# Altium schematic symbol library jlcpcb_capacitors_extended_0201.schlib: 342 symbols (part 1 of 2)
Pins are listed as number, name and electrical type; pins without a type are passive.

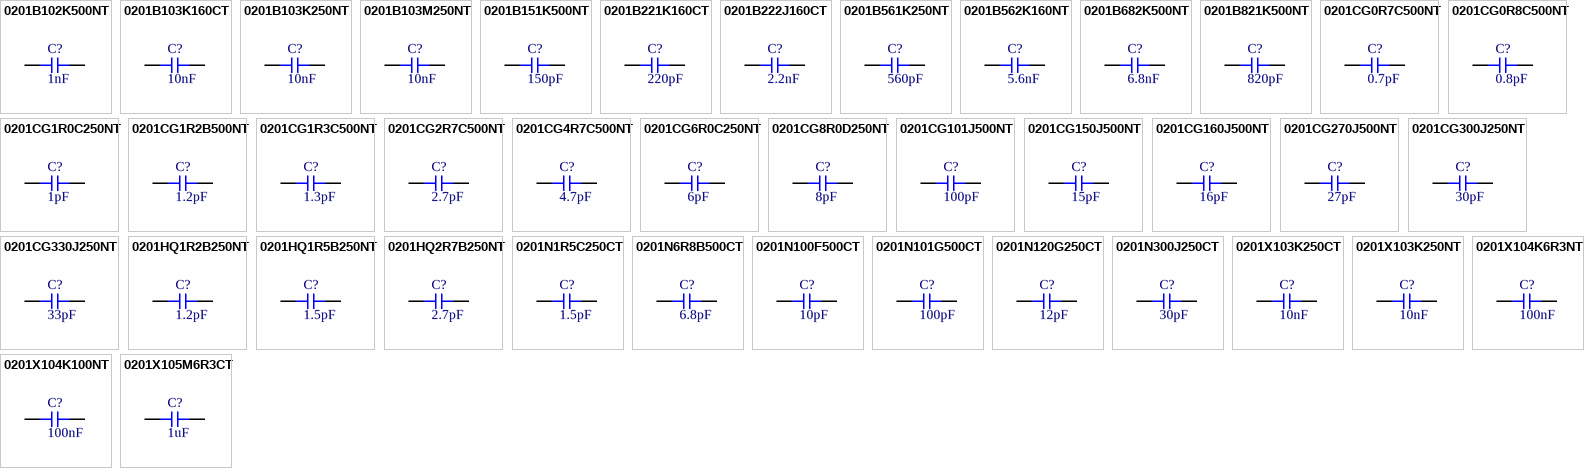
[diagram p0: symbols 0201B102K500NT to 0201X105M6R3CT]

## 0201B102K500NT
designator C?  Capacitance: 1nF  (hidden comment: *)
Capacitor, Ceramic (MLCC), 1nF, ±10%, 50V, X7R, ±10%, SMD 0201; Manufacturer: FH(Guangdong Fenghua Advanced Tech); Manufacturer Part Number: 0201B102K500NT
footprint CAP-0201 (0201 (0603M) Capacitor)
pins: 1, 2

## 0201B103K160CT
designator C?  Capacitance: 10nF  (hidden comment: *)
Capacitor, Ceramic (MLCC), 10nF, ±10%, 16V, X7R, ±10%, SMD 0201; Manufacturer: Walsin Tech Corp; Manufacturer Part Number: 0201B103K160CT
footprint CAP-0201 (0201 (0603M) Capacitor)
pins: 1, 2

## 0201B103K250NT
designator C?  Capacitance: 10nF  (hidden comment: *)
Capacitor, Ceramic (MLCC), 10nF, ±10%, 25V, X7R, ±10%, SMD 0201; Manufacturer: FH(Guangdong Fenghua Advanced Tech); Manufacturer Part Number: 0201B103K250NT
footprint CAP-0201 (0201 (0603M) Capacitor)
pins: 1, 2

## 0201B103M250NT
designator C?  Capacitance: 10nF  (hidden comment: *)
Capacitor, Ceramic (MLCC), 10nF, ±20%, 25V, X7R, ±20%, SMD 0201; Manufacturer: FH (Guangdong Fenghua Advanced Tech); Manufacturer Part Number: 0201B103M250NT
footprint CAP-0201 (0201 (0603M) Capacitor)
pins: 1, 2

## 0201B151K500NT
designator C?  Capacitance: 150pF  (hidden comment: *)
Capacitor, Ceramic (MLCC), 150pF, ±10%, 50V, ±10%, SMD 0201; Manufacturer: FH(Guangdong Fenghua Advanced Tech); Manufacturer Part Number: 0201B151K500NT
footprint CAP-0201 (0201 (0603M) Capacitor)
pins: 1, 2

## 0201B221K160CT
designator C?  Capacitance: 220pF  (hidden comment: *)
Capacitor, Ceramic (MLCC), 220pF, ±10%, 16V, X7R, ±10%, SMD 0201; Manufacturer: Walsin Tech Corp; Manufacturer Part Number: 0201B221K160CT
footprint CAP-0201 (0201 (0603M) Capacitor)
pins: 1, 2

## 0201B222J160CT
designator C?  Capacitance: 2.2nF  (hidden comment: *)
Capacitor, Ceramic (MLCC), 2.2nF, ±5%, 16V, X7R, ±5%, SMD 0201; Manufacturer: Walsin Tech Corp; Manufacturer Part Number: 0201B222J160CT
footprint CAP-0201 (0201 (0603M) Capacitor)
pins: 1, 2

## 0201B561K250NT
designator C?  Capacitance: 560pF  (hidden comment: *)
Capacitor, Ceramic (MLCC), 560pF, ±10%, 25V, X7R, ±10%, SMD 0201; Manufacturer: FH(Guangdong Fenghua Advanced Tech); Manufacturer Part Number: 0201B561K250NT
footprint CAP-0201 (0201 (0603M) Capacitor)
pins: 1, 2

## 0201B562K160NT
designator C?  Capacitance: 5.6nF  (hidden comment: *)
Capacitor, Ceramic (MLCC), 5.6nF, ±10%, 16V, ±10%, SMD 0201; Manufacturer: FH(Guangdong Fenghua Advanced Tech); Manufacturer Part Number: 0201B562K160NT
footprint CAP-0201 (0201 (0603M) Capacitor)
pins: 1, 2

## 0201B682K500NT
designator C?  Capacitance: 6.8nF  (hidden comment: *)
Capacitor, Ceramic (MLCC), 6.8nF, ±10%, 50V, ±10%, SMD 0201; Manufacturer: FH(Guangdong Fenghua Advanced Tech); Manufacturer Part Number: 0201B682K500NT
footprint CAP-0201 (0201 (0603M) Capacitor)
pins: 1, 2

## 0201B821K500NT
designator C?  Capacitance: 820pF  (hidden comment: *)
Capacitor, Ceramic (MLCC), 820pF, ±10%, 50V, ±10%, SMD 0201; Manufacturer: FH(Guangdong Fenghua Advanced Tech); Manufacturer Part Number: 0201B821K500NT
footprint CAP-0201 (0201 (0603M) Capacitor)
pins: 1, 2

## 0201CG0R7C500NT
designator C?  Capacitance: 0.7pF  (hidden comment: *)
Capacitor, Ceramic (MLCC), 0.7pF, ±0.25pF, 50V, ±0.25pF, SMD 0201; Manufacturer: FH(Guangdong Fenghua Advanced Tech); Manufacturer Part Number: 0201CG0R7C500NT
footprint CAP-0201 (0201 (0603M) Capacitor)
pins: 1, 2

## 0201CG0R8C500NT
designator C?  Capacitance: 0.8pF  (hidden comment: *)
Capacitor, Ceramic (MLCC), 0.8pF, ±0.25pF, 50V, ±0.25pF, SMD 0201; Manufacturer: FH(Guangdong Fenghua Advanced Tech); Manufacturer Part Number: 0201CG0R8C500NT
footprint CAP-0201 (0201 (0603M) Capacitor)
pins: 1, 2

## 0201CG1R0C250NT
designator C?  Capacitance: 1pF  (hidden comment: *)
Capacitor, Ceramic (MLCC), 1pF, ±0.25pF, 25V, C0G, ±0.25pF, SMD 0201; Manufacturer: FH(Guangdong Fenghua Advanced Tech); Manufacturer Part Number: 0201CG1R0C250NT
footprint CAP-0201 (0201 (0603M) Capacitor)
pins: 1, 2

## 0201CG1R2B500NT
designator C?  Capacitance: 1.2pF  (hidden comment: *)
Capacitor, Ceramic (MLCC), 1.2pF, ±0.1pF, 50V, C0G, ±0.1pF, SMD 0201; Manufacturer: FH(Guangdong Fenghua Advanced Tech); Manufacturer Part Number: 0201CG1R2B500NT
footprint CAP-0201 (0201 (0603M) Capacitor)
pins: 1, 2

## 0201CG1R3C500NT
designator C?  Capacitance: 1.3pF  (hidden comment: *)
Capacitor, Ceramic (MLCC), 1.3pF, ±0.25pF, 50V, C0G, ±0.25pF, SMD 0201; Manufacturer: FH(Guangdong Fenghua Advanced Tech); Manufacturer Part Number: 0201CG1R3C500NT
footprint CAP-0201 (0201 (0603M) Capacitor)
pins: 1, 2

## 0201CG2R7C500NT
designator C?  Capacitance: 2.7pF  (hidden comment: *)
Capacitor, Ceramic (MLCC), 2.7pF, ±0.25pF, 50V, C0G, ±0.25pF, SMD 0201; Manufacturer: FH(Guangdong Fenghua Advanced Tech); Manufacturer Part Number: 0201CG2R7C500NT
footprint CAP-0201 (0201 (0603M) Capacitor)
pins: 1, 2

## 0201CG4R7C500NT
designator C?  Capacitance: 4.7pF  (hidden comment: *)
Capacitor, Ceramic (MLCC), 4.7pF, ±5%, 50V, C0G, ±5%, SMD 0201; Manufacturer: FH(Guangdong Fenghua Advanced Tech); Manufacturer Part Number: 0201CG4R7C500NT
footprint CAP-0201 (0201 (0603M) Capacitor)
pins: 1, 2

## 0201CG6R0C250NT
designator C?  Capacitance: 6pF  (hidden comment: *)
Capacitor, Ceramic (MLCC), 6pF, ±0.25pF, 25V, ±0.25pF, SMD 0201; Manufacturer: FH(Guangdong Fenghua Advanced Tech); Manufacturer Part Number: 0201CG6R0C250NT
footprint CAP-0201 (0201 (0603M) Capacitor)
pins: 1, 2

## 0201CG8R0D250NT
designator C?  Capacitance: 8pF  (hidden comment: *)
Capacitor, Ceramic (MLCC), 8pF, ±0.5pF, 25V, C0G, ±0.5pF, SMD 0201; Manufacturer: FH(Guangdong Fenghua Advanced Tech); Manufacturer Part Number: 0201CG8R0D250NT
footprint CAP-0201 (0201 (0603M) Capacitor)
pins: 1, 2

## 0201CG101J500NT
designator C?  Capacitance: 100pF  (hidden comment: *)
Capacitor, Ceramic (MLCC), 100pF, ±5%, 50V, C0G, ±5%, SMD 0201; Manufacturer: FH(Guangdong Fenghua Advanced Tech); Manufacturer Part Number: 0201CG101J500NT
footprint CAP-0201 (0201 (0603M) Capacitor)
pins: 1, 2

## 0201CG150J500NT
designator C?  Capacitance: 15pF  (hidden comment: *)
Capacitor, Ceramic (MLCC), 15pF, ±5%, 50V, C0G, ±5%, SMD 0201; Manufacturer: FH(Guangdong Fenghua Advanced Tech); Manufacturer Part Number: 0201CG150J500NT
footprint CAP-0201 (0201 (0603M) Capacitor)
pins: 1, 2

## 0201CG160J500NT
designator C?  Capacitance: 16pF  (hidden comment: *)
Capacitor, Ceramic (MLCC), 16pF, ±5%, 50V, ±5%, SMD 0201; Manufacturer: FH(Guangdong Fenghua Advanced Tech); Manufacturer Part Number: 0201CG160J500NT
footprint CAP-0201 (0201 (0603M) Capacitor)
pins: 1, 2

## 0201CG270J500NT
designator C?  Capacitance: 27pF  (hidden comment: *)
Capacitor, Ceramic (MLCC), 27pF, ±5%, 50V, C0G, ±5%, SMD 0201; Manufacturer: FH(Guangdong Fenghua Advanced Tech); Manufacturer Part Number: 0201CG270J500NT
footprint CAP-0201 (0201 (0603M) Capacitor)
pins: 1, 2

## 0201CG300J250NT
designator C?  Capacitance: 30pF  (hidden comment: *)
Capacitor, Ceramic (MLCC), 30pF, ±5%, 25V, ±5%, SMD 0201; Manufacturer: FH (Guangdong Fenghua Advanced Tech); Manufacturer Part Number: 0201CG300J250NT
footprint CAP-0201 (0201 (0603M) Capacitor)
pins: 1, 2

## 0201CG330J250NT
designator C?  Capacitance: 33pF  (hidden comment: *)
Capacitor, Ceramic (MLCC), 33pF, ±5%, 25V, C0G, ±5%, SMD 0201; Manufacturer: FH(Guangdong Fenghua Advanced Tech); Manufacturer Part Number: 0201CG330J250NT
footprint CAP-0201 (0201 (0603M) Capacitor)
pins: 1, 2

## 0201HQ1R2B250NT
designator C?  Capacitance: 1.2pF  (hidden comment: *)
Capacitor, Ceramic (MLCC), 1.2pF, ±0.1pF, 25V, C0G, ±0.1pF, SMD 0201; Manufacturer: FH(Guangdong Fenghua Advanced Tech); Manufacturer Part Number: 0201HQ1R2B250NT
footprint CAP-0201 (0201 (0603M) Capacitor)
pins: 1, 2

## 0201HQ1R5B250NT
designator C?  Capacitance: 1.5pF  (hidden comment: *)
Capacitor, Ceramic (MLCC), 1.5pF, ±0.1pF, 25V, C0G, ±0.1pF, SMD 0201; Manufacturer: FH(Guangdong Fenghua Advanced Tech); Manufacturer Part Number: 0201HQ1R5B250NT
footprint CAP-0201 (0201 (0603M) Capacitor)
pins: 1, 2

## 0201HQ2R7B250NT
designator C?  Capacitance: 2.7pF  (hidden comment: *)
Capacitor, Ceramic (MLCC), 2.7pF, ±0.1pF, 25V, C0G, ±0.1pF, SMD 0201; Manufacturer: FH(Guangdong Fenghua Advanced Tech); Manufacturer Part Number: 0201HQ2R7B250NT
footprint CAP-0201 (0201 (0603M) Capacitor)
pins: 1, 2

## 0201N1R5C250CT
designator C?  Capacitance: 1.5pF  (hidden comment: *)
Capacitor, Ceramic (MLCC), 1.5pF, ±0.25pF, 25V, NP0, ±0.25pF, SMD 0201; Manufacturer: Walsin Tech Corp; Manufacturer Part Number: 0201N1R5C250CT
footprint CAP-0201 (0201 (0603M) Capacitor)
pins: 1, 2

## 0201N6R8B500CT
designator C?  Capacitance: 6.8pF  (hidden comment: *)
Capacitor, Ceramic (MLCC), 6.8pF, ±0.1pF, 50V, NP0, ±0.1pF, SMD 0201; Manufacturer: Walsin Tech Corp; Manufacturer Part Number: 0201N6R8B500CT
footprint CAP-0201 (0201 (0603M) Capacitor)
pins: 1, 2

## 0201N100F500CT
designator C?  Capacitance: 10pF  (hidden comment: *)
Capacitor, Ceramic (MLCC), 10pF, ±1%, 50V, NP0, ±1%, SMD 0201; Manufacturer: Walsin Tech Corp; Manufacturer Part Number: 0201N100F500CT
footprint CAP-0201 (0201 (0603M) Capacitor)
pins: 1, 2

## 0201N101G500CT
designator C?  Capacitance: 100pF  (hidden comment: *)
Capacitor, Ceramic (MLCC), 100pF, ±2%, 50V, NP0, ±2%, SMD 0201; Manufacturer: Walsin Tech Corp; Manufacturer Part Number: 0201N101G500CT
footprint CAP-0201 (0201 (0603M) Capacitor)
pins: 1, 2

## 0201N120G250CT
designator C?  Capacitance: 12pF  (hidden comment: *)
Capacitor, Ceramic (MLCC), 12pF, ±2%, 25V, NP0, ±2%, SMD 0201; Manufacturer: Walsin Tech Corp; Manufacturer Part Number: 0201N120G250CT
footprint CAP-0201 (0201 (0603M) Capacitor)
pins: 1, 2

## 0201N300J250CT
designator C?  Capacitance: 30pF  (hidden comment: *)
Capacitor, Ceramic (MLCC), 30pF, ±5%, 25V, NP0, ±5%, SMD 0201; Manufacturer: Walsin Tech Corp; Manufacturer Part Number: 0201N300J250CT
footprint CAP-0201 (0201 (0603M) Capacitor)
pins: 1, 2

## 0201X103K250CT
designator C?  Capacitance: 10nF  (hidden comment: *)
Capacitor, Ceramic (MLCC), 10nF, ±10%, 25V, X5R, ±10%, SMD 0201; Manufacturer: Walsin Tech Corp; Manufacturer Part Number: 0201X103K250CT
footprint CAP-0201 (0201 (0603M) Capacitor)
pins: 1, 2

## 0201X103K250NT
designator C?  Capacitance: 10nF  (hidden comment: *)
Capacitor, Ceramic (MLCC), 10nF, ±10%, 25V, ±10%, SMD 0201; Manufacturer: FH(Guangdong Fenghua Advanced Tech); Manufacturer Part Number: 0201X103K250NT
footprint CAP-0201 (0201 (0603M) Capacitor)
pins: 1, 2

## 0201X104K6R3NT
designator C?  Capacitance: 100nF  (hidden comment: *)
Capacitor, Ceramic (MLCC), 100nF, ±10%, 6.3V, X5R, ±10%, SMD 0201; Manufacturer: FH(Guangdong Fenghua Advanced Tech); Manufacturer Part Number: 0201X104K6R3NT
footprint CAP-0201 (0201 (0603M) Capacitor)
pins: 1, 2

## 0201X104K100NT
designator C?  Capacitance: 100nF  (hidden comment: *)
Capacitor, Ceramic (MLCC), 100nF, ±10%, 10V, X5R, ±10%, SMD 0201; Manufacturer: FH(Guangdong Fenghua Advanced Tech); Manufacturer Part Number: 0201X104K100NT
footprint CAP-0201 (0201 (0603M) Capacitor)
pins: 1, 2

## 0201X105M6R3CT
designator C?  Capacitance: 1uF  (hidden comment: *)
Capacitor, Ceramic (MLCC), 1uF, ±20%, 6.3V, X5R, ±20%, SMD 0201; Manufacturer: Walsin Tech Corp; Manufacturer Part Number: 0201X105M6R3CT
footprint CAP-0201 (0201 (0603M) Capacitor)
pins: 1, 2

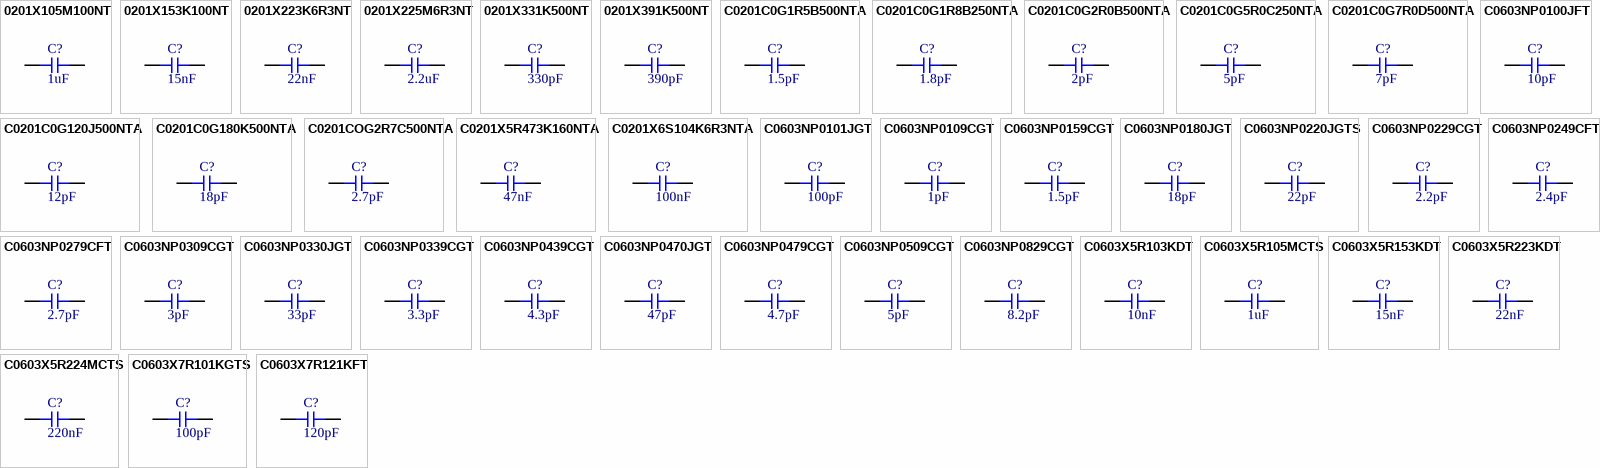
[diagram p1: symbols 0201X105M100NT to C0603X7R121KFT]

## 0201X105M100NT
designator C?  Capacitance: 1uF  (hidden comment: *)
Capacitor, Ceramic (MLCC), 1uF, ±10%, 25V, X5R, ±10%, SMD 0201; Manufacturer: FH (Guangdong Fenghua Advanced Tech); Manufacturer Part Number: 0201X105M100NT
footprint CAP-0201 (0201 (0603M) Capacitor)
pins: 1, 2

## 0201X153K100NT
designator C?  Capacitance: 15nF  (hidden comment: *)
Capacitor, Ceramic (MLCC), 15nF, ±10%, 10V, X5R, ±10%, SMD 0201; Manufacturer: FH(Guangdong Fenghua Advanced Tech); Manufacturer Part Number: 0201X153K100NT
footprint CAP-0201 (0201 (0603M) Capacitor)
pins: 1, 2

## 0201X223K6R3NT
designator C?  Capacitance: 22nF  (hidden comment: *)
Capacitor, Ceramic (MLCC), 22nF, ±10%, 6.3V, X5R, ±10%, SMD 0201; Manufacturer: FH(Guangdong Fenghua Advanced Tech); Manufacturer Part Number: 0201X223K6R3NT
footprint CAP-0201 (0201 (0603M) Capacitor)
pins: 1, 2

## 0201X225M6R3NT
designator C?  Capacitance: 2.2uF  (hidden comment: *)
Capacitor, Ceramic (MLCC), 2.2uF, ±20%, 6.3V, X5R, ±20%, SMD 0201; Manufacturer: FH(Guangdong Fenghua Advanced Tech); Manufacturer Part Number: 0201X225M6R3NT
footprint CAP-0201 (0201 (0603M) Capacitor)
pins: 1, 2

## 0201X331K500NT
designator C?  Capacitance: 330pF  (hidden comment: *)
Capacitor, Ceramic (MLCC), 330pF, ±10%, 50V, ±10%, SMD 0201; Manufacturer: FH(Guangdong Fenghua Advanced Tech); Manufacturer Part Number: 0201X331K500NT
footprint CAP-0201 (0201 (0603M) Capacitor)
pins: 1, 2

## 0201X391K500NT
designator C?  Capacitance: 390pF  (hidden comment: *)
Capacitor, Ceramic (MLCC), 390pF, ±10%, 50V, ±10%, SMD 0201; Manufacturer: FH(Guangdong Fenghua Advanced Tech); Manufacturer Part Number: 0201X391K500NT
footprint CAP-0201 (0201 (0603M) Capacitor)
pins: 1, 2

## C0201C0G1R5B500NTA
designator C?  Capacitance: 1.5pF  (hidden comment: *)
Capacitor, Ceramic (MLCC), 1.5pF, ±0.1pF, 50V, C0G, ±0.1pF, SMD 0201; Manufacturer: EYANG(Shenzhen Eyang Tech Development); Manufacturer Part Number: C0201C0G1R5B500NTA
footprint CAP-0201 (0201 (0603M) Capacitor)
pins: 1, 2

## C0201C0G1R8B250NTA
designator C?  Capacitance: 1.8pF  (hidden comment: *)
Capacitor, Ceramic (MLCC), 1.8pF, ±0.1pF, 25V, C0G, ±0.1pF, SMD 0201; Manufacturer: EYANG(Shenzhen Eyang Tech Development); Manufacturer Part Number: C0201C0G1R8B250NTA
footprint CAP-0201 (0201 (0603M) Capacitor)
pins: 1, 2

## C0201C0G2R0B500NTA
designator C?  Capacitance: 2pF  (hidden comment: *)
Capacitor, Ceramic (MLCC), 2pF, ±0.1pF, 50V, C0G, ±0.1pF, SMD 0201; Manufacturer: EYANG(Shenzhen Eyang Tech Development); Manufacturer Part Number: C0201C0G2R0B500NTA
footprint CAP-0201 (0201 (0603M) Capacitor)
pins: 1, 2

## C0201C0G5R0C250NTA
designator C?  Capacitance: 5pF  (hidden comment: *)
Capacitor, Ceramic (MLCC), 5pF, ±0.25pF, 25V, C0G, ±0.25pF, SMD 0201; Manufacturer: EYANG(Shenzhen Eyang Tech Development); Manufacturer Part Number: C0201C0G5R0C250NTA
footprint CAP-0201 (0201 (0603M) Capacitor)
pins: 1, 2

## C0201C0G7R0D500NTA
designator C?  Capacitance: 7pF  (hidden comment: *)
Capacitor, Ceramic (MLCC), 7pF, ±0.5pF, 50V, C0G, ±0.5pF, SMD 0201; Manufacturer: EYANG(Shenzhen Eyang Tech Development); Manufacturer Part Number: C0201C0G7R0D500NTA
footprint CAP-0201 (0201 (0603M) Capacitor)
pins: 1, 2

## C0201C0G120J500NTA
designator C?  Capacitance: 12pF  (hidden comment: *)
Capacitor, Ceramic (MLCC), 12pF, ±5%, 50V, C0G, ±5%, SMD 0201; Manufacturer: EYANG(Shenzhen Eyang Tech Development); Manufacturer Part Number: C0201C0G120J500NTA
footprint CAP-0201 (0201 (0603M) Capacitor)
pins: 1, 2

## C0201C0G180K500NTA
designator C?  Capacitance: 18pF  (hidden comment: *)
Capacitor, Ceramic (MLCC), 18pF, ±10%, 50V, C0G, ±10%, SMD 0201; Manufacturer: EYANG(Shenzhen Eyang Tech Development); Manufacturer Part Number: C0201C0G180K500NTA
footprint CAP-0201 (0201 (0603M) Capacitor)
pins: 1, 2

## C0201COG2R7C500NTA
designator C?  Capacitance: 2.7pF  (hidden comment: *)
Capacitor, Ceramic (MLCC), 2.7pF, ±0.25pF, 50V, C0G, ±0.25pF, SMD 0201; Manufacturer: EYANG(Shenzhen Eyang Tech Development); Manufacturer Part Number: C0201COG2R7C500NTA
footprint CAP-0201 (0201 (0603M) Capacitor)
pins: 1, 2

## C0201X5R473K160NTA
designator C?  Capacitance: 47nF  (hidden comment: *)
Capacitor, Ceramic (MLCC), 47nF, ±10%, 16V, X5R, ±10%, SMD 0201; Manufacturer: EYANG(Shenzhen Eyang Tech Development); Manufacturer Part Number: C0201X5R473K160NTA
footprint CAP-0201 (0201 (0603M) Capacitor)
pins: 1, 2

## C0201X6S104K6R3NTA
designator C?  Capacitance: 100nF  (hidden comment: *)
Capacitor, Ceramic (MLCC), 100nF, ±10%, 6.3V, X6S, ±10%, SMD 0201; Manufacturer: EYANG(Shenzhen Eyang Tech Development); Manufacturer Part Number: C0201X6S104K6R3NTA
footprint CAP-0201 (0201 (0603M) Capacitor)
pins: 1, 2

## C0603NP0100JFT
designator C?  Capacitance: 10pF  (hidden comment: *)
Capacitor, Ceramic (MLCC), 10pF, ±5%, 25V, NP0, ±5%, SMD 0201; Manufacturer: Darfon Elec; Manufacturer Part Number: C0603NP0100JFT
footprint CAP-0201 (0201 (0603M) Capacitor)
pins: 1, 2

## C0603NP0101JGT
designator C?  Capacitance: 100pF  (hidden comment: *)
Capacitor, Ceramic (MLCC), 100pF, ±5%, 50V, NP0, ±5%, SMD 0201; Manufacturer: Darfon Elec; Manufacturer Part Number: C0603NP0101JGT
footprint CAP-0201 (0201 (0603M) Capacitor)
pins: 1, 2

## C0603NP0109CGT
designator C?  Capacitance: 1pF  (hidden comment: *)
Capacitor, Ceramic (MLCC), 1pF, ±0.25pF, 50V, NP0, ±0.25pF, SMD 0201; Manufacturer: Darfon Elec; Manufacturer Part Number: C0603NP0109CGT
footprint CAP-0201 (0201 (0603M) Capacitor)
pins: 1, 2

## C0603NP0159CGT
designator C?  Capacitance: 1.5pF  (hidden comment: *)
Capacitor, Ceramic (MLCC), 1.5pF, ±0.25pF, 50V, NP0, ±0.25pF, SMD 0201; Manufacturer: Darfon Elec; Manufacturer Part Number: C0603NP0159CGT
footprint CAP-0201 (0201 (0603M) Capacitor)
pins: 1, 2

## C0603NP0180JGT
designator C?  Capacitance: 18pF  (hidden comment: *)
Capacitor, Ceramic (MLCC), 18pF, ±5%, 50V, NP0, ±5%, SMD 0201; Manufacturer: Darfon Elec; Manufacturer Part Number: C0603NP0180JGT
footprint CAP-0201 (0201 (0603M) Capacitor)
pins: 1, 2

## C0603NP0220JGTS
designator C?  Capacitance: 22pF  (hidden comment: *)
Capacitor, Ceramic (MLCC), 22pF, ±5%, 50V, NP0, ±5%, SMD 0201; Manufacturer: Darfon Elec; Manufacturer Part Number: C0603NP0220JGTS
footprint CAP-0201 (0201 (0603M) Capacitor)
pins: 1, 2

## C0603NP0229CGT
designator C?  Capacitance: 2.2pF  (hidden comment: *)
Capacitor, Ceramic (MLCC), 2.2pF, ±0.25pF, 50V, NP0, ±0.25pF, SMD 0201; Manufacturer: Darfon Elec; Manufacturer Part Number: C0603NP0229CGT
footprint CAP-0201 (0201 (0603M) Capacitor)
pins: 1, 2

## C0603NP0249CFT
designator C?  Capacitance: 2.4pF  (hidden comment: *)
Capacitor, Ceramic (MLCC), 2.4pF, ±0.25pF, 25V, NP0, ±0.25pF, SMD 0201; Manufacturer: Darfon Elec; Manufacturer Part Number: C0603NP0249CFT
footprint CAP-0201 (0201 (0603M) Capacitor)
pins: 1, 2

## C0603NP0279CFT
designator C?  Capacitance: 2.7pF  (hidden comment: *)
Capacitor, Ceramic (MLCC), 2.7pF, ±0.25pF, 25V, NP0, ±0.25pF, SMD 0201; Manufacturer: Darfon Elec; Manufacturer Part Number: C0603NP0279CFT
footprint CAP-0201 (0201 (0603M) Capacitor)
pins: 1, 2

## C0603NP0309CGT
designator C?  Capacitance: 3pF  (hidden comment: *)
Capacitor, Ceramic (MLCC), 3pF, ±0.25pF, 50V, NP0, ±0.25pF, SMD 0201; Manufacturer: Darfon Elec; Manufacturer Part Number: C0603NP0309CGT
footprint CAP-0201 (0201 (0603M) Capacitor)
pins: 1, 2

## C0603NP0330JGT
designator C?  Capacitance: 33pF  (hidden comment: *)
Capacitor, Ceramic (MLCC), 33pF, ±5%, 50V, NP0, ±5%, SMD 0201; Manufacturer: Darfon Elec; Manufacturer Part Number: C0603NP0330JGT
footprint CAP-0201 (0201 (0603M) Capacitor)
pins: 1, 2

## C0603NP0339CGT
designator C?  Capacitance: 3.3pF  (hidden comment: *)
Capacitor, Ceramic (MLCC), 3.3pF, ±0.25pF, 50V, NP0, ±0.25pF, SMD 0201; Manufacturer: Darfon Elec; Manufacturer Part Number: C0603NP0339CGT
footprint CAP-0201 (0201 (0603M) Capacitor)
pins: 1, 2

## C0603NP0439CGT
designator C?  Capacitance: 4.3pF  (hidden comment: *)
Capacitor, Ceramic (MLCC), 4.3pF, ±0.25pF, 50V, NP0, ±0.25pF, SMD 0201; Manufacturer: Darfon Elec; Manufacturer Part Number: C0603NP0439CGT
footprint CAP-0201 (0201 (0603M) Capacitor)
pins: 1, 2

## C0603NP0470JGT
designator C?  Capacitance: 47pF  (hidden comment: *)
Capacitor, Ceramic (MLCC), 47pF, ±5%, 50V, NP0, ±5%, SMD 0201; Manufacturer: Darfon Elec; Manufacturer Part Number: C0603NP0470JGT
footprint CAP-0201 (0201 (0603M) Capacitor)
pins: 1, 2

## C0603NP0479CGT
designator C?  Capacitance: 4.7pF  (hidden comment: *)
Capacitor, Ceramic (MLCC), 4.7pF, ±0.25pF, 50V, NP0, ±0.25pF, SMD 0201; Manufacturer: Darfon Elec; Manufacturer Part Number: C0603NP0479CGT
footprint CAP-0201 (0201 (0603M) Capacitor)
pins: 1, 2

## C0603NP0509CGT
designator C?  Capacitance: 5pF  (hidden comment: *)
Capacitor, Ceramic (MLCC), 5pF, ±0.25pF, 50V, NP0, ±0.25pF, SMD 0201; Manufacturer: Darfon Elec; Manufacturer Part Number: C0603NP0509CGT
footprint CAP-0201 (0201 (0603M) Capacitor)
pins: 1, 2

## C0603NP0829CGT
designator C?  Capacitance: 8.2pF  (hidden comment: *)
Capacitor, Ceramic (MLCC), 8.2pF, ±0.25pF, 50V, NP0, ±0.25pF, SMD 0201; Manufacturer: Darfon Elec; Manufacturer Part Number: C0603NP0829CGT
footprint CAP-0201 (0201 (0603M) Capacitor)
pins: 1, 2

## C0603X5R103KDT
designator C?  Capacitance: 10nF  (hidden comment: *)
Capacitor, Ceramic (MLCC), 10nF, ±10%, 10V, X5R, ±10%, SMD 0201; Manufacturer: Darfon Elec; Manufacturer Part Number: C0603X5R103KDT
footprint CAP-0201 (0201 (0603M) Capacitor)
pins: 1, 2

## C0603X5R105MCTS
designator C?  Capacitance: 1uF  (hidden comment: *)
Capacitor, Ceramic (MLCC), 1uF, ±20%, 6.3V, X5R, ±20%, SMD 0201; Manufacturer: Darfon Elec; Manufacturer Part Number: C0603X5R105MCTS
footprint CAP-0201 (0201 (0603M) Capacitor)
pins: 1, 2

## C0603X5R153KDT
designator C?  Capacitance: 15nF  (hidden comment: *)
Capacitor, Ceramic (MLCC), 15nF, ±10%, 10V, X5R, ±10%, SMD 0201; Manufacturer: Darfon Elec; Manufacturer Part Number: C0603X5R153KDT
footprint CAP-0201 (0201 (0603M) Capacitor)
pins: 1, 2

## C0603X5R223KDT
designator C?  Capacitance: 22nF  (hidden comment: *)
Capacitor, Ceramic (MLCC), 22nF, ±10%, 10V, X5R, ±10%, SMD 0201; Manufacturer: Darfon Elec; Manufacturer Part Number: C0603X5R223KDT
footprint CAP-0201 (0201 (0603M) Capacitor)
pins: 1, 2

## C0603X5R224MCTS
designator C?  Capacitance: 220nF  (hidden comment: *)
Capacitor, Ceramic (MLCC), 220nF, ±20%, 6.3V, X5R, ±20%, SMD 0201; Manufacturer: Darfon Elec; Manufacturer Part Number: C0603X5R224MCTS
footprint CAP-0201 (0201 (0603M) Capacitor)
pins: 1, 2

## C0603X7R101KGTS
designator C?  Capacitance: 100pF  (hidden comment: *)
Capacitor, Ceramic (MLCC), 100pF, ±10%, 50V, X7R, ±10%, SMD 0201; Manufacturer: Darfon Elec; Manufacturer Part Number: C0603X7R101KGTS
footprint CAP-0201 (0201 (0603M) Capacitor)
pins: 1, 2

## C0603X7R121KFT
designator C?  Capacitance: 120pF  (hidden comment: *)
Capacitor, Ceramic (MLCC), 120pF, ±10%, 25V, X7R, ±10%, SMD 0201; Manufacturer: Darfon Elec; Manufacturer Part Number: C0603X7R121KFT
footprint CAP-0201 (0201 (0603M) Capacitor)
pins: 1, 2

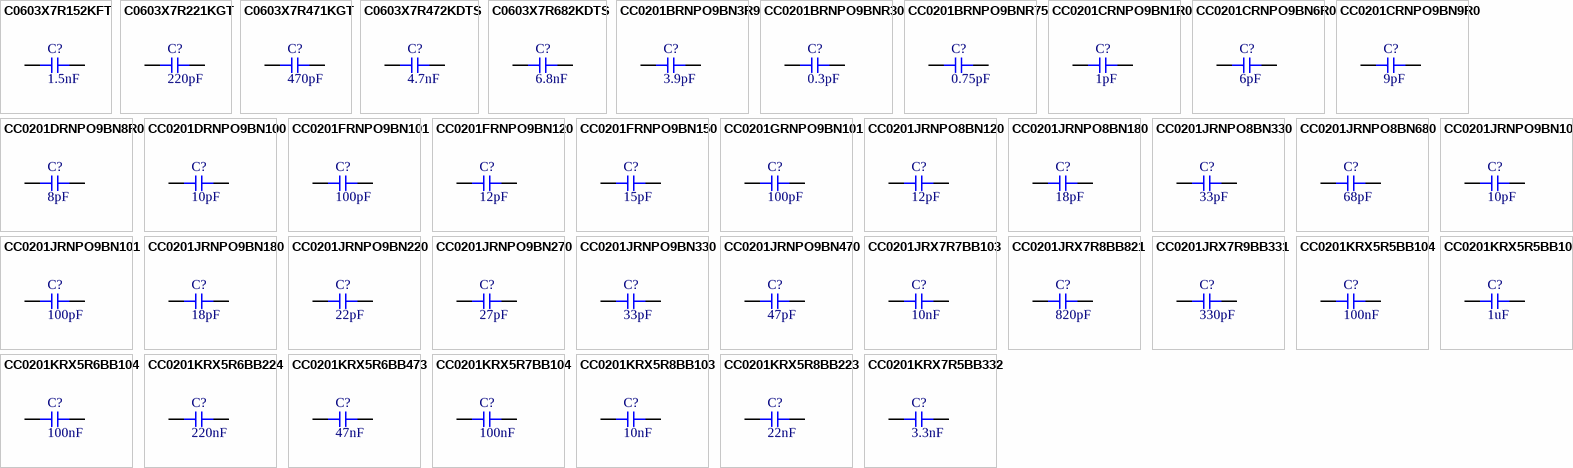
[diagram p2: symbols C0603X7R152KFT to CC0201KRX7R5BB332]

## C0603X7R152KFT
designator C?  Capacitance: 1.5nF  (hidden comment: *)
Capacitor, Ceramic (MLCC), 1.5nF, ±10%, 25V, X7R, ±10%, SMD 0201; Manufacturer: Darfon Elec; Manufacturer Part Number: C0603X7R152KFT
footprint CAP-0201 (0201 (0603M) Capacitor)
pins: 1, 2

## C0603X7R221KGT
designator C?  Capacitance: 220pF  (hidden comment: *)
Capacitor, Ceramic (MLCC), 220pF, ±10%, 50V, X7R, ±10%, SMD 0201; Manufacturer: Darfon Elec; Manufacturer Part Number: C0603X7R221KGT
footprint CAP-0201 (0201 (0603M) Capacitor)
pins: 1, 2

## C0603X7R471KGT
designator C?  Capacitance: 470pF  (hidden comment: *)
Capacitor, Ceramic (MLCC), 470pF, ±10%, 50V, X7R, ±10%, SMD 0201; Manufacturer: Darfon Elec; Manufacturer Part Number: C0603X7R471KGT
footprint CAP-0201 (0201 (0603M) Capacitor)
pins: 1, 2

## C0603X7R472KDTS
designator C?  Capacitance: 4.7nF  (hidden comment: *)
Capacitor, Ceramic (MLCC), 4.7nF, ±10%, 10V, X7R, ±10%, SMD 0201; Manufacturer: Darfon Elec; Manufacturer Part Number: C0603X7R472KDTS
footprint CAP-0201 (0201 (0603M) Capacitor)
pins: 1, 2

## C0603X7R682KDTS
designator C?  Capacitance: 6.8nF  (hidden comment: *)
Capacitor, Ceramic (MLCC), 6.8nF, ±10%, 10V, X7R, ±10%, SMD 0201; Manufacturer: Darfon Elec; Manufacturer Part Number: C0603X7R682KDTS
footprint CAP-0201 (0201 (0603M) Capacitor)
pins: 1, 2

## CC0201BRNPO9BN3R9
designator C?  Capacitance: 3.9pF  (hidden comment: *)
Capacitor, Ceramic (MLCC), 3.9pF, ±0.1pF, 50V, NP0, ±0.1pF, SMD 0201; Manufacturer: YAGEO; Manufacturer Part Number: CC0201BRNPO9BN3R9
footprint CAP-0201 (0201 (0603M) Capacitor)
pins: 1, 2

## CC0201BRNPO9BNR30
designator C?  Capacitance: 0.3pF  (hidden comment: *)
Capacitor, Ceramic (MLCC), 0.3pF, ±0.1pF, 50V, NP0, ±0.1pF, SMD 0201; Manufacturer: YAGEO; Manufacturer Part Number: CC0201BRNPO9BNR30
footprint CAP-0201 (0201 (0603M) Capacitor)
pins: 1, 2

## CC0201BRNPO9BNR75
designator C?  Capacitance: 0.75pF  (hidden comment: *)
Capacitor, Ceramic (MLCC), 0.75pF, ±0.1pF, 50V, NP0, ±0.1pF, SMD 0201; Manufacturer: YAGEO; Manufacturer Part Number: CC0201BRNPO9BNR75
footprint CAP-0201 (0201 (0603M) Capacitor)
pins: 1, 2

## CC0201CRNPO9BN1R0
designator C?  Capacitance: 1pF  (hidden comment: *)
Capacitor, Ceramic (MLCC), 1pF, ±0.25pF, 50V, NP0, ±0.25pF, SMD 0201; Manufacturer: YAGEO; Manufacturer Part Number: CC0201CRNPO9BN1R0
footprint CAP-0201 (0201 (0603M) Capacitor)
pins: 1, 2

## CC0201CRNPO9BN6R0
designator C?  Capacitance: 6pF  (hidden comment: *)
Capacitor, Ceramic (MLCC), 6pF, ±0.25pF, 50V, NP0, ±0.25pF, SMD 0201; Manufacturer: YAGEO; Manufacturer Part Number: CC0201CRNPO9BN6R0
footprint CAP-0201 (0201 (0603M) Capacitor)
pins: 1, 2

## CC0201CRNPO9BN9R0
designator C?  Capacitance: 9pF  (hidden comment: *)
Capacitor, Ceramic (MLCC), 9pF, ±0.25pF, 50V, NP0, ±0.25pF, SMD 0201; Manufacturer: YAGEO; Manufacturer Part Number: CC0201CRNPO9BN9R0
footprint CAP-0201 (0201 (0603M) Capacitor)
pins: 1, 2

## CC0201DRNPO9BN8R0
designator C?  Capacitance: 8pF  (hidden comment: *)
Capacitor, Ceramic (MLCC), 8pF, ±0.5pF, 50V, NP0, ±0.5pF, SMD 0201; Manufacturer: YAGEO; Manufacturer Part Number: CC0201DRNPO9BN8R0
footprint CAP-0201 (0201 (0603M) Capacitor)
pins: 1, 2

## CC0201DRNPO9BN100
designator C?  Capacitance: 10pF  (hidden comment: *)
Capacitor, Ceramic (MLCC), 10pF, ±0.5pF, 50V, NP0, ±0.5pF, SMD 0201; Manufacturer: YAGEO; Manufacturer Part Number: CC0201DRNPO9BN100
footprint CAP-0201 (0201 (0603M) Capacitor)
pins: 1, 2

## CC0201FRNPO9BN101
designator C?  Capacitance: 100pF  (hidden comment: *)
Capacitor, Ceramic (MLCC), 100pF, ±1pF, 50V, NP0, ±1pF, SMD 0201; Manufacturer: YAGEO; Manufacturer Part Number: CC0201FRNPO9BN101
footprint CAP-0201 (0201 (0603M) Capacitor)
pins: 1, 2

## CC0201FRNPO9BN120
designator C?  Capacitance: 12pF  (hidden comment: *)
Capacitor, Ceramic (MLCC), 12pF, ±1%, 50V, NP0, ±1%, SMD 0201; Manufacturer: YAGEO; Manufacturer Part Number: CC0201FRNPO9BN120
footprint CAP-0201 (0201 (0603M) Capacitor)
pins: 1, 2

## CC0201FRNPO9BN150
designator C?  Capacitance: 15pF  (hidden comment: *)
Capacitor, Ceramic (MLCC), 15pF, ±1pF, 50V, NP0, ±1pF, SMD 0201; Manufacturer: YAGEO; Manufacturer Part Number: CC0201FRNPO9BN150
footprint CAP-0201 (0201 (0603M) Capacitor)
pins: 1, 2

## CC0201GRNPO9BN101
designator C?  Capacitance: 100pF  (hidden comment: *)
Capacitor, Ceramic (MLCC), 100pF, ±2%, 50V, NP0, ±2%, SMD 0201; Manufacturer: YAGEO; Manufacturer Part Number: CC0201GRNPO9BN101
footprint CAP-0201 (0201 (0603M) Capacitor)
pins: 1, 2

## CC0201JRNPO8BN120
designator C?  Capacitance: 12pF  (hidden comment: *)
Capacitor, Ceramic (MLCC), 12pF, ±5%, 25V, NP0, ±5%, SMD 0201; Manufacturer: YAGEO; Manufacturer Part Number: CC0201JRNPO8BN120
footprint CAP-0201 (0201 (0603M) Capacitor)
pins: 1, 2

## CC0201JRNPO8BN180
designator C?  Capacitance: 18pF  (hidden comment: *)
Capacitor, Ceramic (MLCC), 18pF, ±5%, 25V, NP0, ±5%, SMD 0201; Manufacturer: YAGEO; Manufacturer Part Number: CC0201JRNPO8BN180
footprint CAP-0201 (0201 (0603M) Capacitor)
pins: 1, 2

## CC0201JRNPO8BN330
designator C?  Capacitance: 33pF  (hidden comment: *)
Capacitor, Ceramic (MLCC), 33pF, ±5%, 25V, NP0, ±5%, SMD 0201; Manufacturer: YAGEO; Manufacturer Part Number: CC0201JRNPO8BN330
footprint CAP-0201 (0201 (0603M) Capacitor)
pins: 1, 2

## CC0201JRNPO8BN680
designator C?  Capacitance: 68pF  (hidden comment: *)
Capacitor, Ceramic (MLCC), 68pF, ±5%, 25V, NP0, ±5%, SMD 0201; Manufacturer: YAGEO; Manufacturer Part Number: CC0201JRNPO8BN680
footprint CAP-0201 (0201 (0603M) Capacitor)
pins: 1, 2

## CC0201JRNPO9BN100
designator C?  Capacitance: 10pF  (hidden comment: *)
Capacitor, Ceramic (MLCC), 10pF, ±5%, 50V, NP0, ±5%, SMD 0201; Manufacturer: YAGEO; Manufacturer Part Number: CC0201JRNPO9BN100
footprint CAP-0201 (0201 (0603M) Capacitor)
pins: 1, 2

## CC0201JRNPO9BN101
designator C?  Capacitance: 100pF  (hidden comment: *)
Capacitor, Ceramic (MLCC), 100pF, ±5%, 50V, NP0, ±5%, SMD 0201; Manufacturer: YAGEO; Manufacturer Part Number: CC0201JRNPO9BN101
footprint CAP-0201 (0201 (0603M) Capacitor)
pins: 1, 2

## CC0201JRNPO9BN180
designator C?  Capacitance: 18pF  (hidden comment: *)
Capacitor, Ceramic (MLCC), 18pF, ±5%, 50V, NP0, ±5%, SMD 0201; Manufacturer: YAGEO; Manufacturer Part Number: CC0201JRNPO9BN180
footprint CAP-0201 (0201 (0603M) Capacitor)
pins: 1, 2

## CC0201JRNPO9BN220
designator C?  Capacitance: 22pF  (hidden comment: *)
Capacitor, Ceramic (MLCC), 22pF, ±5%, 50V, NP0, ±5%, SMD 0201; Manufacturer: YAGEO; Manufacturer Part Number: CC0201JRNPO9BN220
footprint CAP-0201 (0201 (0603M) Capacitor)
pins: 1, 2

## CC0201JRNPO9BN270
designator C?  Capacitance: 27pF  (hidden comment: *)
Capacitor, Ceramic (MLCC), 27pF, ±5%, 50V, NP0, ±5%, SMD 0201; Manufacturer: YAGEO; Manufacturer Part Number: CC0201JRNPO9BN270
footprint CAP-0201 (0201 (0603M) Capacitor)
pins: 1, 2

## CC0201JRNPO9BN330
designator C?  Capacitance: 33pF  (hidden comment: *)
Capacitor, Ceramic (MLCC), 33pF, ±5%, 50V, NP0, ±5%, SMD 0201; Manufacturer: YAGEO; Manufacturer Part Number: CC0201JRNPO9BN330
footprint CAP-0201 (0201 (0603M) Capacitor)
pins: 1, 2

## CC0201JRNPO9BN470
designator C?  Capacitance: 47pF  (hidden comment: *)
Capacitor, Ceramic (MLCC), 47pF, ±5%, 50V, NP0, ±5%, SMD 0201; Manufacturer: YAGEO; Manufacturer Part Number: CC0201JRNPO9BN470
footprint CAP-0201 (0201 (0603M) Capacitor)
pins: 1, 2

## CC0201JRX7R7BB103
designator C?  Capacitance: 10nF  (hidden comment: *)
Capacitor, Ceramic (MLCC), 10nF, ±5%, 16V, X7R, ±5%, SMD 0201; Manufacturer: YAGEO; Manufacturer Part Number: CC0201JRX7R7BB103
footprint CAP-0201 (0201 (0603M) Capacitor)
pins: 1, 2

## CC0201JRX7R8BB821
designator C?  Capacitance: 820pF  (hidden comment: *)
Capacitor, Ceramic (MLCC), 820pF, ±5%, 25V, X7R, ±5%, SMD 0201; Manufacturer: YAGEO; Manufacturer Part Number: CC0201JRX7R8BB821
footprint CAP-0201 (0201 (0603M) Capacitor)
pins: 1, 2

## CC0201JRX7R9BB331
designator C?  Capacitance: 330pF  (hidden comment: *)
Capacitor, Ceramic (MLCC), 330pF, ±5%, 50V, X7R, ±5%, SMD 0201; Manufacturer: YAGEO; Manufacturer Part Number: CC0201JRX7R9BB331
footprint CAP-0201 (0201 (0603M) Capacitor)
pins: 1, 2

## CC0201KRX5R5BB104
designator C?  Capacitance: 100nF  (hidden comment: *)
Capacitor, Ceramic (MLCC), 100nF, ±10%, 6.3V, X5R, ±10%, SMD 0201; Manufacturer: YAGEO; Manufacturer Part Number: CC0201KRX5R5BB104
footprint CAP-0201 (0201 (0603M) Capacitor)
pins: 1, 2

## CC0201KRX5R5BB105
designator C?  Capacitance: 1uF  (hidden comment: *)
Capacitor, Ceramic (MLCC), 1uF, ±10%, 6.3V, X5R, ±10%, SMD 0201; Manufacturer: YAGEO; Manufacturer Part Number: CC0201KRX5R5BB105
footprint CAP-0201 (0201 (0603M) Capacitor)
pins: 1, 2

## CC0201KRX5R6BB104
designator C?  Capacitance: 100nF  (hidden comment: *)
Capacitor, Ceramic (MLCC), 100nF, ±10%, 10V, X5R, ±10%, SMD 0201; Manufacturer: YAGEO; Manufacturer Part Number: CC0201KRX5R6BB104
footprint CAP-0201 (0201 (0603M) Capacitor)
pins: 1, 2

## CC0201KRX5R6BB224
designator C?  Capacitance: 220nF  (hidden comment: *)
Capacitor, Ceramic (MLCC), 220nF, ±10%, 10V, X5R, ±10%, SMD 0201; Manufacturer: YAGEO; Manufacturer Part Number: CC0201KRX5R6BB224
footprint CAP-0201 (0201 (0603M) Capacitor)
pins: 1, 2

## CC0201KRX5R6BB473
designator C?  Capacitance: 47nF  (hidden comment: *)
Capacitor, Ceramic (MLCC), 47nF, ±10%, 10V, X5R, ±10%, SMD 0201; Manufacturer: YAGEO; Manufacturer Part Number: CC0201KRX5R6BB473
footprint CAP-0201 (0201 (0603M) Capacitor)
pins: 1, 2

## CC0201KRX5R7BB104
designator C?  Capacitance: 100nF  (hidden comment: *)
Capacitor, Ceramic (MLCC), 100nF, ±10%, 16V, X5R, ±10%, SMD 0201; Manufacturer: YAGEO; Manufacturer Part Number: CC0201KRX5R7BB104
footprint CAP-0201 (0201 (0603M) Capacitor)
pins: 1, 2

## CC0201KRX5R8BB103
designator C?  Capacitance: 10nF  (hidden comment: *)
Capacitor, Ceramic (MLCC), 10nF, ±10%, 25V, X5R, ±10%, SMD 0201; Manufacturer: YAGEO; Manufacturer Part Number: CC0201KRX5R8BB103
footprint CAP-0201 (0201 (0603M) Capacitor)
pins: 1, 2

## CC0201KRX5R8BB223
designator C?  Capacitance: 22nF  (hidden comment: *)
Capacitor, Ceramic (MLCC), 22nF, ±10%, 25V, X5R, ±10%, SMD 0201; Manufacturer: YAGEO; Manufacturer Part Number: CC0201KRX5R8BB223
footprint CAP-0201 (0201 (0603M) Capacitor)
pins: 1, 2

## CC0201KRX7R5BB332
designator C?  Capacitance: 3.3nF  (hidden comment: *)
Capacitor, Ceramic (MLCC), 3.3nF, ±10%, 6.3V, X7R, ±10%, SMD 0201; Manufacturer: YAGEO; Manufacturer Part Number: CC0201KRX7R5BB332
footprint CAP-0201 (0201 (0603M) Capacitor)
pins: 1, 2

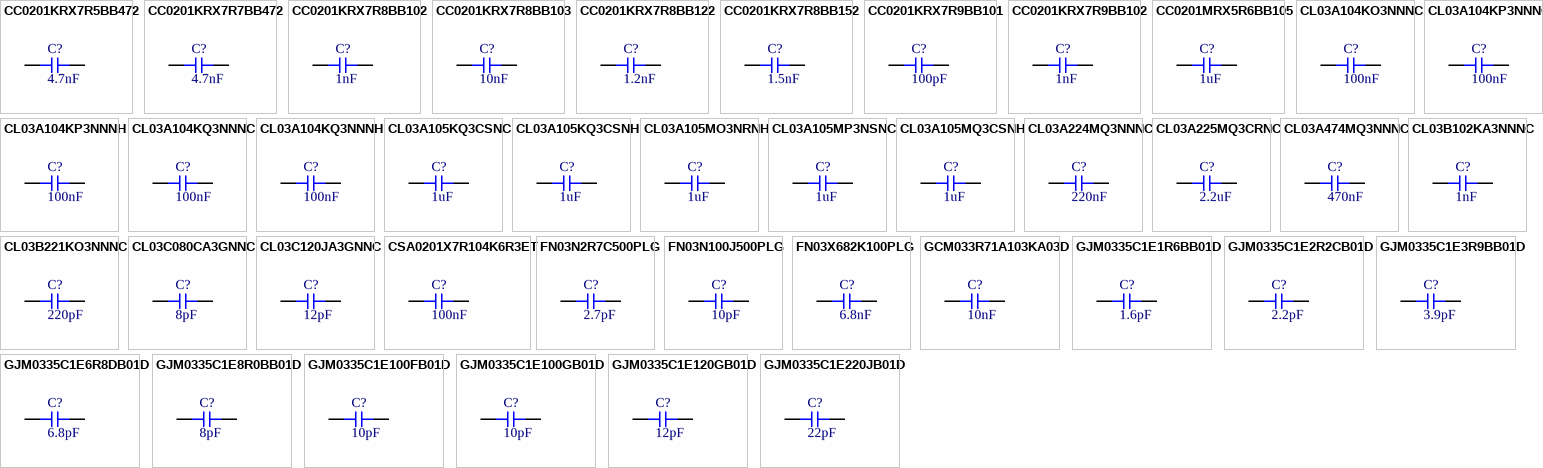
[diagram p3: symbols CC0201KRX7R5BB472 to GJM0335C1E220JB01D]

## CC0201KRX7R5BB472
designator C?  Capacitance: 4.7nF  (hidden comment: *)
Capacitor, Ceramic (MLCC), 4.7nF, ±10%, 6.3V, X7R, ±10%, SMD 0201; Manufacturer: YAGEO; Manufacturer Part Number: CC0201KRX7R5BB472
footprint CAP-0201 (0201 (0603M) Capacitor)
pins: 1, 2

## CC0201KRX7R7BB472
designator C?  Capacitance: 4.7nF  (hidden comment: *)
Capacitor, Ceramic (MLCC), 4.7nF, ±10%, 16V, X7R, ±10%, SMD 0201; Manufacturer: YAGEO; Manufacturer Part Number: CC0201KRX7R7BB472
footprint CAP-0201 (0201 (0603M) Capacitor)
pins: 1, 2

## CC0201KRX7R8BB102
designator C?  Capacitance: 1nF  (hidden comment: *)
Capacitor, Ceramic (MLCC), 1nF, ±10%, 25V, X7R, ±10%, SMD 0201; Manufacturer: YAGEO; Manufacturer Part Number: CC0201KRX7R8BB102
footprint CAP-0201 (0201 (0603M) Capacitor)
pins: 1, 2

## CC0201KRX7R8BB103
designator C?  Capacitance: 10nF  (hidden comment: *)
Capacitor, Ceramic (MLCC), 10nF, ±10%, 25V, X7R, ±10%, SMD 0201; Manufacturer: YAGEO; Manufacturer Part Number: CC0201KRX7R8BB103
footprint CAP-0201 (0201 (0603M) Capacitor)
pins: 1, 2

## CC0201KRX7R8BB122
designator C?  Capacitance: 1.2nF  (hidden comment: *)
Capacitor, Ceramic (MLCC), 1.2nF, ±10%, 25V, X7R, ±10%, SMD 0201; Manufacturer: YAGEO; Manufacturer Part Number: CC0201KRX7R8BB122
footprint CAP-0201 (0201 (0603M) Capacitor)
pins: 1, 2

## CC0201KRX7R8BB152
designator C?  Capacitance: 1.5nF  (hidden comment: *)
Capacitor, Ceramic (MLCC), 1.5nF, ±10%, 25V, X7R, ±10%, SMD 0201; Manufacturer: YAGEO; Manufacturer Part Number: CC0201KRX7R8BB152
footprint CAP-0201 (0201 (0603M) Capacitor)
pins: 1, 2

## CC0201KRX7R9BB101
designator C?  Capacitance: 100pF  (hidden comment: *)
Capacitor, Ceramic (MLCC), 100pF, ±10%, 50V, X7R, ±10%, SMD 0201; Manufacturer: YAGEO; Manufacturer Part Number: CC0201KRX7R9BB101
footprint CAP-0201 (0201 (0603M) Capacitor)
pins: 1, 2

## CC0201KRX7R9BB102
designator C?  Capacitance: 1nF  (hidden comment: *)
Capacitor, Ceramic (MLCC), 1nF, ±10%, 50V, X7R, ±10%, SMD 0201; Manufacturer: YAGEO; Manufacturer Part Number: CC0201KRX7R9BB102
footprint CAP-0201 (0201 (0603M) Capacitor)
pins: 1, 2

## CC0201MRX5R6BB105
designator C?  Capacitance: 1uF  (hidden comment: *)
Capacitor, Ceramic (MLCC), 1uF, ±20%, 10V, X5R, ±20%, SMD 0201; Manufacturer: YAGEO; Manufacturer Part Number: CC0201MRX5R6BB105
footprint CAP-0201 (0201 (0603M) Capacitor)
pins: 1, 2

## CL03A104KO3NNNC
designator C?  Capacitance: 100nF  (hidden comment: *)
Capacitor, Ceramic (MLCC), 100nF, ±10%, 16V, X5R, ±10%, SMD 0201; Manufacturer: Samsung Electro-Mechanics; Manufacturer Part Number: CL03A104KO3NNNC
footprint CAP-0201 (0201 (0603M) Capacitor)
pins: 1, 2

## CL03A104KP3NNNC
designator C?  Capacitance: 100nF  (hidden comment: *)
Capacitor, Ceramic (MLCC), 100nF, ±10%, 10V, X5R, ±10%, SMD 0201; Manufacturer: Samsung Electro-Mechanics; Manufacturer Part Number: CL03A104KP3NNNC
footprint CAP-0201 (0201 (0603M) Capacitor)
pins: 1, 2

## CL03A104KP3NNNH
designator C?  Capacitance: 100nF  (hidden comment: *)
Capacitor, Ceramic (MLCC), 100nF, ±10%, 10V, X5R, ±10%, SMD 0201; Manufacturer: Samsung Electro-Mechanics; Manufacturer Part Number: CL03A104KP3NNNH
footprint CAP-0201 (0201 (0603M) Capacitor)
pins: 1, 2

## CL03A104KQ3NNNC
designator C?  Capacitance: 100nF  (hidden comment: *)
Capacitor, Ceramic (MLCC), 100nF, ±10%, 6.3V, X5R, ±10%, SMD 0201; Manufacturer: Samsung Electro-Mechanics; Manufacturer Part Number: CL03A104KQ3NNNC
footprint CAP-0201 (0201 (0603M) Capacitor)
pins: 1, 2

## CL03A104KQ3NNNH
designator C?  Capacitance: 100nF  (hidden comment: *)
Capacitor, Ceramic (MLCC), 100nF, ±10%, 6.3V, X5R, ±10%, SMD 0201; Manufacturer: Samsung Electro-Mechanics; Manufacturer Part Number: CL03A104KQ3NNNH
footprint CAP-0201 (0201 (0603M) Capacitor)
pins: 1, 2

## CL03A105KQ3CSNC
designator C?  Capacitance: 1uF  (hidden comment: *)
Capacitor, Ceramic (MLCC), 1uF, ±10%, 6.3V, X5R, ±10%, SMD 0201; Manufacturer: Samsung Electro-Mechanics; Manufacturer Part Number: CL03A105KQ3CSNC
footprint CAP-0201 (0201 (0603M) Capacitor)
pins: 1, 2

## CL03A105KQ3CSNH
designator C?  Capacitance: 1uF  (hidden comment: *)
Capacitor, Ceramic (MLCC), 1uF, ±10%, 6.3V, X5R, ±10%, SMD 0201; Manufacturer: Samsung Electro-Mechanics; Manufacturer Part Number: CL03A105KQ3CSNH
footprint CAP-0201 (0201 (0603M) Capacitor)
pins: 1, 2

## CL03A105MO3NRNH
designator C?  Capacitance: 1uF  (hidden comment: *)
Capacitor, Ceramic (MLCC), 1uF, ±20%, 16V, X5R, ±20%, SMD 0201; Manufacturer: Samsung Electro-Mechanics; Manufacturer Part Number: CL03A105MO3NRNH
footprint CAP-0201 (0201 (0603M) Capacitor)
pins: 1, 2

## CL03A105MP3NSNC
designator C?  Capacitance: 1uF  (hidden comment: *)
Capacitor, Ceramic (MLCC), 1uF, ±20%, 10V, X5R, ±20%, SMD 0201; Manufacturer: Samsung Electro-Mechanics; Manufacturer Part Number: CL03A105MP3NSNC
footprint CAP-0201 (0201 (0603M) Capacitor)
pins: 1, 2

## CL03A105MQ3CSNH
designator C?  Capacitance: 1uF  (hidden comment: *)
Capacitor, Ceramic (MLCC), 1uF, ±20%, 6.3V, X5R, ±20%, SMD 0201; Manufacturer: Samsung Electro-Mechanics; Manufacturer Part Number: CL03A105MQ3CSNH
footprint CAP-0201 (0201 (0603M) Capacitor)
pins: 1, 2

## CL03A224MQ3NNNC
designator C?  Capacitance: 220nF  (hidden comment: *)
Capacitor, Ceramic (MLCC), 220nF, ±20%, 6.3V, X5R, ±20%, SMD 0201; Manufacturer: Samsung Electro-Mechanics; Manufacturer Part Number: CL03A224MQ3NNNC
footprint CAP-0201 (0201 (0603M) Capacitor)
pins: 1, 2

## CL03A225MQ3CRNC
designator C?  Capacitance: 2.2uF  (hidden comment: *)
Capacitor, Ceramic (MLCC), 2.2uF, ±20%, 6.3V, X5R, ±20%, SMD 0201; Manufacturer: Samsung Electro-Mechanics; Manufacturer Part Number: CL03A225MQ3CRNC
footprint CAP-0201 (0201 (0603M) Capacitor)
pins: 1, 2

## CL03A474MQ3NNNC
designator C?  Capacitance: 470nF  (hidden comment: *)
Capacitor, Ceramic (MLCC), 470nF, ±20%, 6.3V, X5R, ±20%, SMD 0201; Manufacturer: Samsung Electro-Mechanics; Manufacturer Part Number: CL03A474MQ3NNNC
footprint CAP-0201 (0201 (0603M) Capacitor)
pins: 1, 2

## CL03B102KA3NNNC
designator C?  Capacitance: 1nF  (hidden comment: *)
Capacitor, Ceramic (MLCC), 1nF, ±10%, 25V, X7R, ±10%, SMD 0201; Manufacturer: Samsung Electro-Mechanics; Manufacturer Part Number: CL03B102KA3NNNC
footprint CAP-0201 (0201 (0603M) Capacitor)
pins: 1, 2

## CL03B221KO3NNNC
designator C?  Capacitance: 220pF  (hidden comment: *)
Capacitor, Ceramic (MLCC), 220pF, ±10%, 16V, X7R, ±10%, SMD 0201; Manufacturer: Samsung Electro-Mechanics; Manufacturer Part Number: CL03B221KO3NNNC
footprint CAP-0201 (0201 (0603M) Capacitor)
pins: 1, 2

## CL03C080CA3GNNC
designator C?  Capacitance: 8pF  (hidden comment: *)
Capacitor, Ceramic (MLCC), 8pF, ±0.25pF, 25V, C0G, ±0.25pF, SMD 0201; Manufacturer: Samsung Electro-Mechanics; Manufacturer Part Number: CL03C080CA3GNNC
footprint CAP-0201 (0201 (0603M) Capacitor)
pins: 1, 2

## CL03C120JA3GNNC
designator C?  Capacitance: 12pF  (hidden comment: *)
Capacitor, Ceramic (MLCC), 12pF, ±5%, 25V, C0G, ±5%, SMD 0201; Manufacturer: Samsung Electro-Mechanics; Manufacturer Part Number: CL03C120JA3GNNC
footprint CAP-0201 (0201 (0603M) Capacitor)
pins: 1, 2

## CSA0201X7R104K6R3ET
designator C?  Capacitance: 100nF  (hidden comment: *)
Capacitor, Ceramic (MLCC), 100nF, ±10%, 6.3V, X7R, ±10%, SMD 0201; Manufacturer: HRE; Manufacturer Part Number: CSA0201X7R104K6R3ET
footprint CAP-0201 (0201 (0603M) Capacitor)
pins: 1, 2

## FN03N2R7C500PLG
designator C?  Capacitance: 2.7pF  (hidden comment: *)
Capacitor, Ceramic (MLCC), 2.7pF, ±0.25pF, 50V, C0G, ±0.25pF, SMD 0201; Manufacturer: PSA(Prosperity Dielectrics); Manufacturer Part Number: FN03N2R7C500PLG
footprint CAP-0201 (0201 (0603M) Capacitor)
pins: 1, 2

## FN03N100J500PLG
designator C?  Capacitance: 10pF  (hidden comment: *)
Capacitor, Ceramic (MLCC), 10pF, ±5%, 50V, ±5%, SMD 0201; Manufacturer: PSA(Prosperity Dielectrics); Manufacturer Part Number: FN03N100J500PLG
footprint CAP-0201 (0201 (0603M) Capacitor)
pins: 1, 2

## FN03X682K100PLG
designator C?  Capacitance: 6.8nF  (hidden comment: *)
Capacitor, Ceramic (MLCC), 6.8nF, ±10%, 10V, X7R, ±10%, SMD 0201; Manufacturer: PSA(Prosperity Dielectrics); Manufacturer Part Number: FN03X682K100PLG
footprint CAP-0201 (0201 (0603M) Capacitor)
pins: 1, 2

## GCM033R71A103KA03D
designator C?  Capacitance: 10nF  (hidden comment: *)
Capacitor, Ceramic (MLCC), 10nF, ±10%, ±10%, SMD 0201; Manufacturer: Murata Electronics; Manufacturer Part Number: GCM033R71A103KA03D
footprint CAP-0201 (0201 (0603M) Capacitor)
pins: 1, 2

## GJM0335C1E1R6BB01D
designator C?  Capacitance: 1.6pF  (hidden comment: *)
Capacitor, Ceramic (MLCC), 1.6pF, ±0.1pF, 25V, C0G, ±0.1pF, SMD 0201; Manufacturer: Murata Electronics; Manufacturer Part Number: GJM0335C1E1R6BB01D
footprint CAP-0201 (0201 (0603M) Capacitor)
pins: 1, 2

## GJM0335C1E2R2CB01D
designator C?  Capacitance: 2.2pF  (hidden comment: *)
Capacitor, Ceramic (MLCC), 2.2pF, ±0.25pF, ±0.25pF, SMD 0201; Manufacturer: Murata Electronics; Manufacturer Part Number: GJM0335C1E2R2CB01D
footprint CAP-0201 (0201 (0603M) Capacitor)
pins: 1, 2

## GJM0335C1E3R9BB01D
designator C?  Capacitance: 3.9pF  (hidden comment: *)
Capacitor, Ceramic (MLCC), 3.9pF, ±0.1pF, ±0.1pF, SMD 0201; Manufacturer: Murata Electronics; Manufacturer Part Number: GJM0335C1E3R9BB01D
footprint CAP-0201 (0201 (0603M) Capacitor)
pins: 1, 2

## GJM0335C1E6R8DB01D
designator C?  Capacitance: 6.8pF  (hidden comment: *)
Capacitor, Ceramic (MLCC), 6.8pF, ±0.5pF, ±0.5pF, SMD 0201; Manufacturer: Murata Electronics; Manufacturer Part Number: GJM0335C1E6R8DB01D
footprint CAP-0201 (0201 (0603M) Capacitor)
pins: 1, 2

## GJM0335C1E8R0BB01D
designator C?  Capacitance: 8pF  (hidden comment: *)
Capacitor, Ceramic (MLCC), 8pF, ±0.1pF, 25V, C0G, ±0.1pF, SMD 0201; Manufacturer: Murata Electronics; Manufacturer Part Number: GJM0335C1E8R0BB01D
footprint CAP-0201 (0201 (0603M) Capacitor)
pins: 1, 2

## GJM0335C1E100FB01D
designator C?  Capacitance: 10pF  (hidden comment: *)
Capacitor, Ceramic (MLCC), 10pF, ±1%, 25V, C0G, ±1%, SMD 0201; Manufacturer: Murata Electronics; Manufacturer Part Number: GJM0335C1E100FB01D
footprint CAP-0201 (0201 (0603M) Capacitor)
pins: 1, 2

## GJM0335C1E100GB01D
designator C?  Capacitance: 10pF  (hidden comment: *)
Capacitor, Ceramic (MLCC), 10pF, ±2%, 25V, C0G, ±2%, SMD 0201; Manufacturer: Murata Electronics; Manufacturer Part Number: GJM0335C1E100GB01D
footprint CAP-0201 (0201 (0603M) Capacitor)
pins: 1, 2

## GJM0335C1E120GB01D
designator C?  Capacitance: 12pF  (hidden comment: *)
Capacitor, Ceramic (MLCC), 12pF, ±2%, 25V, X6S, ±2%, SMD 0201; Manufacturer: Murata Electronics; Manufacturer Part Number: GJM0335C1E120GB01D
footprint CAP-0201 (0201 (0603M) Capacitor)
pins: 1, 2

## GJM0335C1E220JB01D
designator C?  Capacitance: 22pF  (hidden comment: *)
Capacitor, Ceramic (MLCC), 22pF, ±5%, 25V, C0G, ±5%, SMD 0201; Manufacturer: Murata Electronics; Manufacturer Part Number: GJM0335C1E220JB01D
footprint CAP-0201 (0201 (0603M) Capacitor)
pins: 1, 2

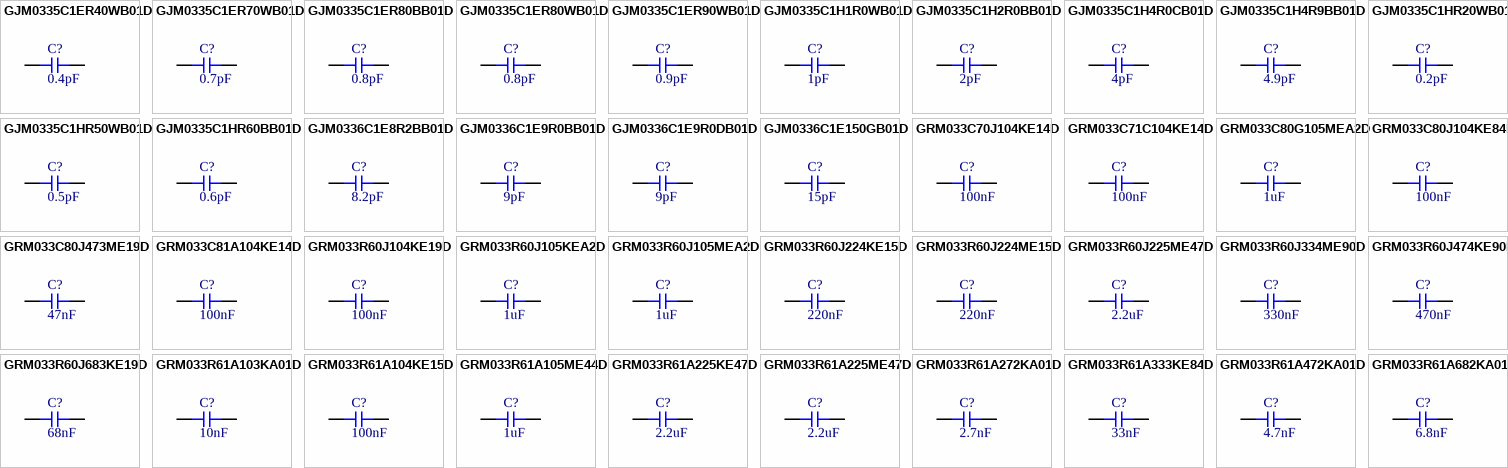
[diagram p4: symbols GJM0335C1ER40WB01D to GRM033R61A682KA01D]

## GJM0335C1ER40WB01D
designator C?  Capacitance: 0.4pF  (hidden comment: *)
Capacitor, Ceramic (MLCC), 0.4pF, ±0.05pF, 25V, C0G, ±0.05pF, SMD 0201; Manufacturer: Murata Electronics; Manufacturer Part Number: GJM0335C1ER40WB01D
footprint CAP-0201 (0201 (0603M) Capacitor)
pins: 1, 2

## GJM0335C1ER70WB01D
designator C?  Capacitance: 0.7pF  (hidden comment: *)
Capacitor, Ceramic (MLCC), 0.7pF, SMD 0201; Manufacturer: Murata Electronics; Manufacturer Part Number: GJM0335C1ER70WB01D
footprint CAP-0201 (0201 (0603M) Capacitor)
pins: 1, 2

## GJM0335C1ER80BB01D
designator C?  Capacitance: 0.8pF  (hidden comment: *)
Capacitor, Ceramic (MLCC), 0.8pF, ±0.1pF, 25V, C0G, ±0.1pF, SMD 0201; Manufacturer: Murata Electronics; Manufacturer Part Number: GJM0335C1ER80BB01D
footprint CAP-0201 (0201 (0603M) Capacitor)
pins: 1, 2

## GJM0335C1ER80WB01D
designator C?  Capacitance: 0.8pF  (hidden comment: *)
Capacitor, Ceramic (MLCC), 0.8pF, ±0.05pF, 25V, C0G, ±0.05pF, SMD 0201; Manufacturer: Murata Electronics; Manufacturer Part Number: GJM0335C1ER80WB01D
footprint CAP-0201 (0201 (0603M) Capacitor)
pins: 1, 2

## GJM0335C1ER90WB01D
designator C?  Capacitance: 0.9pF  (hidden comment: *)
Capacitor, Ceramic (MLCC), 0.9pF, ±0.05pF, 25V, C0G, ±0.05pF, SMD 0201; Manufacturer: Murata Electronics; Manufacturer Part Number: GJM0335C1ER90WB01D
footprint CAP-0201 (0201 (0603M) Capacitor)
pins: 1, 2

## GJM0335C1H1R0WB01D
designator C?  Capacitance: 1pF  (hidden comment: *)
Capacitor, Ceramic (MLCC), 1pF, ±0.05pF, 50V, C0G, ±0.05pF, SMD 0201; Manufacturer: Murata Electronics; Manufacturer Part Number: GJM0335C1H1R0WB01D
footprint CAP-0201 (0201 (0603M) Capacitor)
pins: 1, 2

## GJM0335C1H2R0BB01D
designator C?  Capacitance: 2pF  (hidden comment: *)
Capacitor, Ceramic (MLCC), 2pF, ±0.1pF, ±0.1pF, SMD 0201; Manufacturer: Murata Electronics; Manufacturer Part Number: GJM0335C1H2R0BB01D
footprint CAP-0201 (0201 (0603M) Capacitor)
pins: 1, 2

## GJM0335C1H4R0CB01D
designator C?  Capacitance: 4pF  (hidden comment: *)
Capacitor, Ceramic (MLCC), 4pF, ±0.25pF, 50V, C0G, ±0.25pF, SMD 0201; Manufacturer: Murata Electronics; Manufacturer Part Number: GJM0335C1H4R0CB01D
footprint CAP-0201 (0201 (0603M) Capacitor)
pins: 1, 2

## GJM0335C1H4R9BB01D
designator C?  Capacitance: 4.9pF  (hidden comment: *)
Capacitor, Ceramic (MLCC), 4.9pF, ±0.1pF, 50V, ±0.1pF, SMD 0201; Manufacturer: Murata Electronics; Manufacturer Part Number: GJM0335C1H4R9BB01D
footprint CAP-0201 (0201 (0603M) Capacitor)
pins: 1, 2

## GJM0335C1HR20WB01D
designator C?  Capacitance: 0.2pF  (hidden comment: *)
Capacitor, Ceramic (MLCC), 0.2pF, ±0.05pF, 50V, C0G, ±0.05pF, SMD 0201; Manufacturer: Murata Electronics; Manufacturer Part Number: GJM0335C1HR20WB01D
footprint CAP-0201 (0201 (0603M) Capacitor)
pins: 1, 2

## GJM0335C1HR50WB01D
designator C?  Capacitance: 0.5pF  (hidden comment: *)
Capacitor, Ceramic (MLCC), 0.5pF, SMD 0201; Manufacturer: Murata Electronics; Manufacturer Part Number: GJM0335C1HR50WB01D
footprint CAP-0201 (0201 (0603M) Capacitor)
pins: 1, 2

## GJM0335C1HR60BB01D
designator C?  Capacitance: 0.6pF  (hidden comment: *)
Capacitor, Ceramic (MLCC), 0.6pF, ±0.1pF, 50V, C0G, ±0.1pF, SMD 0201; Manufacturer: Murata Electronics; Manufacturer Part Number: GJM0335C1HR60BB01D
footprint CAP-0201 (0201 (0603M) Capacitor)
pins: 1, 2

## GJM0336C1E8R2BB01D
designator C?  Capacitance: 8.2pF  (hidden comment: *)
Capacitor, Ceramic (MLCC), 8.2pF, ±0.1pF, 25V, C0H, ±0.1pF, SMD 0201; Manufacturer: Murata Electronics; Manufacturer Part Number: GJM0336C1E8R2BB01D
footprint CAP-0201 (0201 (0603M) Capacitor)
pins: 1, 2

## GJM0336C1E9R0BB01D
designator C?  Capacitance: 9pF  (hidden comment: *)
Capacitor, Ceramic (MLCC), 9pF, ±0.1pF, 25V, C0H, ±0.1pF, SMD 0201; Manufacturer: Murata Electronics; Manufacturer Part Number: GJM0336C1E9R0BB01D
footprint CAP-0201 (0201 (0603M) Capacitor)
pins: 1, 2

## GJM0336C1E9R0DB01D
designator C?  Capacitance: 9pF  (hidden comment: *)
Capacitor, Ceramic (MLCC), 9pF, ±0.5pF, 25V, C0H, ±0.5pF, SMD 0201; Manufacturer: Murata Electronics; Manufacturer Part Number: GJM0336C1E9R0DB01D
footprint CAP-0201 (0201 (0603M) Capacitor)
pins: 1, 2

## GJM0336C1E150GB01D
designator C?  Capacitance: 15pF  (hidden comment: *)
Capacitor, Ceramic (MLCC), 15pF, ±2%, 25V, C0H, ±2%, SMD 0201; Manufacturer: Murata Electronics; Manufacturer Part Number: GJM0336C1E150GB01D
footprint CAP-0201 (0201 (0603M) Capacitor)
pins: 1, 2

## GRM033C70J104KE14D
designator C?  Capacitance: 100nF  (hidden comment: *)
Capacitor, Ceramic (MLCC), 100nF, ±10%, 6.3V, X7S, ±10%, SMD 0201; Manufacturer: Murata Electronics; Manufacturer Part Number: GRM033C70J104KE14D
footprint CAP-0201 (0201 (0603M) Capacitor)
pins: 1, 2

## GRM033C71C104KE14D
designator C?  Capacitance: 100nF  (hidden comment: *)
Capacitor, Ceramic (MLCC), 100nF, ±10%, 16V, X7S, ±10%, SMD 0201; Manufacturer: Murata Electronics; Manufacturer Part Number: GRM033C71C104KE14D
footprint CAP-0201 (0201 (0603M) Capacitor)
pins: 1, 2

## GRM033C80G105MEA2D
designator C?  Capacitance: 1uF  (hidden comment: *)
Capacitor, Ceramic (MLCC), 1uF, ±20%, 4V, X6S, ±20%, SMD 0201; Manufacturer: Murata Electronics; Manufacturer Part Number: GRM033C80G105MEA2D
footprint CAP-0201 (0201 (0603M) Capacitor)
pins: 1, 2

## GRM033C80J104KE84D
designator C?  Capacitance: 100nF  (hidden comment: *)
Capacitor, Ceramic (MLCC), 100nF, ±10%, 6.3V, X6S, ±10%, SMD 0201; Manufacturer: Murata Electronics; Manufacturer Part Number: GRM033C80J104KE84D
footprint CAP-0201 (0201 (0603M) Capacitor)
pins: 1, 2

## GRM033C80J473ME19D
designator C?  Capacitance: 47nF  (hidden comment: *)
Capacitor, Ceramic (MLCC), 47nF, ±20%, ±20%, SMD 0201; Manufacturer: Murata Electronics; Manufacturer Part Number: GRM033C80J473ME19D
footprint CAP-0201 (0201 (0603M) Capacitor)
pins: 1, 2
